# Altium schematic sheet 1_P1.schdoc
size 309 x 223 mm; Symbol: Sheet-Symbol_A4_ByronAP; Device: A4T; @Project Name: Alternator Regulator Field Controller; @Schematic Name: Schematic1; Page Size: A4; @Page Count: 1; @Update Date: 2025-04-14; @Create Date: 2025-04-13; @Page No: 1; @Page Name: P1; Company: ByronAP; Version: 1.0; Drawn: Allen Byron Penner; @Board Name: Board1; @Create Time: 21:01:51; @Update Time: 09:47:18
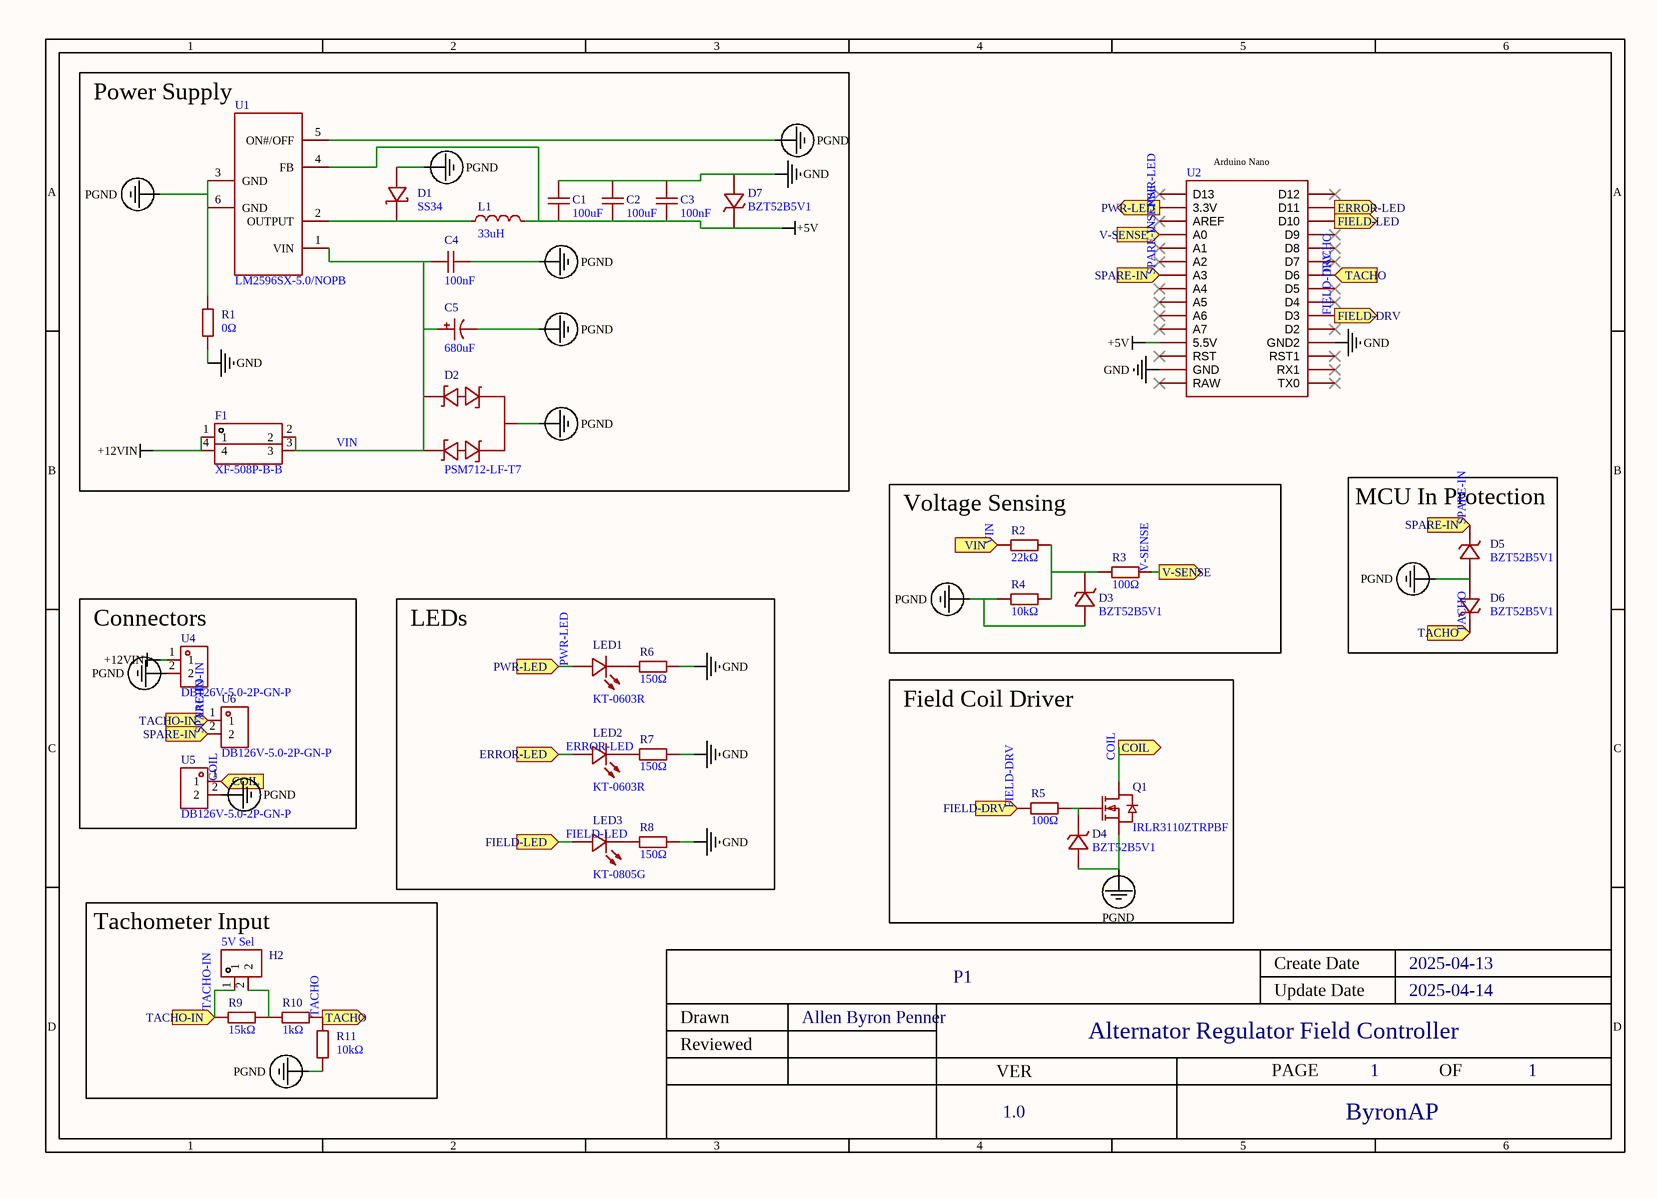
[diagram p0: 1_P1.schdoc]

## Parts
C1  100uF  [C1206]
C2  100uF  [C1206]
C3  100nF  [C1206]
C4  100nF  [C1206]
C5  680uF  [CAP-TH_BD10.0-P5.00-D1.0-FD]
D1  SS34  [SMA_L4.3-W2.6-LS5.2-RD]
D2  PSM712-LF-T7  [SOT-23-3_L3.0-W1.7-P0.95-LS2.9-BR]
D3  BZT52B5V1  [SOD-123_L2.7-W1.6-LS3.7-RD]
D4  BZT52B5V1  [SOD-123_L2.7-W1.6-LS3.7-RD]
D5  BZT52B5V1  [SOD-123_L2.7-W1.6-LS3.7-RD]
D6  BZT52B5V1  [SOD-123_L2.7-W1.6-LS3.7-RD]
D7  BZT52B5V1  [SOD-123_L2.7-W1.6-LS3.7-RD]
F1  XF-508P-B-B  [FUSE-TH_4P-L16.0-W6.7]
H2  PZ254V-11-02P  [HDR-TH_2P-P2.54-V-M]  (value not drawn)
L1  33uH  [IND-SMD_L10.8-W10.0_SLO1040H]
LED1  KT-0603R  [LED0603-RD]
LED2  KT-0603R  [LED0603-RD]
LED3  KT-0805G  [LED0805-R-RD]
Q1  IRLR3110ZTRPBF  [TO-252-3_L6.5-W5.8-P4.58-BL]
R1  0Ω  [R0805]
R2  22kΩ  [R0805]
R3  100Ω  [R0805]
R4  10kΩ  [R0805]
R5  100Ω  [R0805]
R6  150Ω  [R0805]
R7  150Ω  [R0805]
R8  150Ω  [R0805]
R9  15kΩ  [R0805]
R10  1kΩ  [R0805]
R11  10kΩ  [R0805]
U1  LM2596SX-5.0/NOPB  [TO-263-5_L10.2-W8.9-P1.70-TL]
U2  NANO  [NANO]  (value not drawn)
U4  DB126V-5.0-2P-GN-P  [CONN-TH_2P-P5.00_L7.8-W10.0]
U5  DB126V-5.0-2P-GN-P  [CONN-TH_2P-P5.00_L7.8-W10.0]
U6  DB126V-5.0-2P-GN-P  [CONN-TH_2P-P5.00_L7.8-W10.0]

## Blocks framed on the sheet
Power Supply: C1-C5 D1 D2 D7 F1 L1 R1 U1
Voltage Sensing: D3 R2-R4
MCU In Protection: D5 D6
Connectors: U4-U6
LEDs: LED1-LED3 R6-R8
Field Coil Driver: D4 Q1 R5
Tachometer Input: H2 R9-R11

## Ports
COIL (in), COIL (out), ERROR-LED (in), ERROR-LED (out), FIELD-DRV (in), FIELD-DRV (out), FIELD-LED (in), FIELD-LED (out), PWR-LED (in), PWR-LED (out), SPARE-IN (in), TACHO (in), TACHO (out), TACHO-IN (in), V-SENSE (in), V-SENSE (out), VIN (in)

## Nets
+5V: C1.1 C2.1 C3.1 D7.1(K) L1.2 U1.4(FB) U2.5V(5.5V)
+12VIN: F1.1 F1.4 U4.1
GND: C1.2 C2.2 C3.2 D7.2(A) R1.1 R6.2 R7.2 R8.2 U2.GND U2.GND1(GND2)
PGND: C4.2 C5.2 D1.2(A) D2.3(K) D3.2(A) D4.2(A) D5.2(A) D6.2(A) Q1.3(S) R1.2 R4.1 R11.1 U1.3(GND) U1.5(ON#/OFF) U1.6(GND) U4.2 U5.2
COIL: Q1.2(D) U5.1 ; port COIL
ERROR-LED: LED2.2(A) U2.D11 ; port ERROR-LED
FIELD-DRV: R5.1 U2.D3 ; port FIELD-DRV
FIELD-LED: LED3.1(A) U2.D10 ; port FIELD-LED
PWR-LED: LED1.2(A) U2.3.3V ; port PWR-LED
SPARE-IN: D5.1(K) U2.A3 U6.2 ; port SPARE-IN
TACHO: D6.1(K) R10.2 R11.2 U2.D6 ; port TACHO
TACHO-IN: H2.1 R9.1 U6.1 ; port TACHO-IN
V-SENSE: R3.2 U2.A0 ; port V-SENSE
VIN: C4.1 C5.1 D2.1(A1) D2.2(A1) F1.2 F1.3 R2.1 U1.1(VIN) ; port VIN
NetD1_1: D1.1(K) L1.1 U1.2(OUTPUT)
NetD3_1: D3.1(K) R2.2 R3.1 R4.2
NetD4_1: D4.1(K) Q1.1(G) R5.2
NetH2_2: H2.2 R9.2 R10.1
NetLED1_1: LED1.1(K) R6.1
NetLED2_1: LED2.1(K) R7.1
NetLED3_2: LED3.2(K) R8.1

Not connected (* = marked no-connect by the designer): U2 A1* A2* A4* A5* A6* A7* AREF* D2* D4* D5* D7* D8* D9* D12* D13* RAW* RST* RST1* RX1* TX0*

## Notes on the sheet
- (near H2) 5V Sel

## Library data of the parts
C1 C2 = CL31A107MQHNNNE: Manufacturer: SAMSUNG(三星); Add into BOM: yes; Tolerance: ±20%
C3 C4 = CL31B104KBCNNNC: Manufacturer: SAMSUNG(三星); Add into BOM: yes; Tolerance: ±10%
C5 = ERF1EM681G16OT: Manufacturer: AISHI(艾华集团); Add into BOM: yes; Tolerance: ±20%; Voltage Rating: 25V; Pin Spacing: 5mm; Lifetime: 5000hrs@105℃
D1 = SS34_C8678: Manufacturer: MDD(辰达半导体); Add into BOM: yes; Diode Configuration: Independent Type; Forward Voltage (Vf@If): 550mV@3A; Reverse Voltage (Vr): 40V; Rectified Current: 3A; Reverse Leakage Current (Ir): 500uA@40V
D2 = PSM712-LF-T7_C32677: Manufacturer: PROTEK; Add into BOM: yes; Reverse Stand-Off Voltage (Vrwm): 12V; Clamping Voltage: 19V; Voltage - Breakdown: 13.3V; Type: TVS
D3-D7 = BZT52B5V1_C19077393: Manufacturer: 宏嘉诚; Add into BOM: yes; Diode Configuration: Independent Type; Zener Voltage(Nom): 5.1V; Reverse Leakage Current (Ir): 2uA@2V; Zener Voltage(Range): 5V~5.2V; Pd - Power Dissipation(Pd): 500mW; Impedance(Zzt): 60Ω
F1 = XF-508P-B-B: Manufacturer: XFCN(兴飞); Add into BOM: yes
H2 = PZ254V-11-02P: Manufacturer: XFCN(兴飞); Add into BOM: yes; Pin Structure: 1x2P; Pitch: 2.54mm; Circluar Pins/Square Pins: Policy
L1 = SLO1040H330MTT: Manufacturer: Sunltech(韩国顺磁); Add into BOM: yes; Tolerance: ±20%
LED1 LED2 = KT-0603R: Manufacturer: KENTO; Add into BOM: yes; Emitted Color: Red
LED3 = KT-0805G: Manufacturer: KENTO; Symbol: 0805G (Green); Add into BOM: yes; Emitted Color: Emerald
Q1 = IRLR3110ZTRPBF: Manufacturer: Infineon(英飞凌); Add into BOM: yes; Type: 1 N-Channel; Drain Source On Resistance (RDS(on)@Vgs,Id): 14mΩ@10V,38A; Gate Threshold Voltage (Vgs(th)@Id): 2.5V@100uA; Total Gate Charge (Qg@Vgs): 48nC; Input Capacitance (Ciss@Vds): 3980pF; Reverse Transfer Capacitance (Crss@Vds): 130pF
R1 = 0805W8F0000T5E_C17477: Manufacturer: UNI-ROYAL(厚声); Add into BOM: yes; Tolerance: ±1%; Temperature Coefficient: ±800ppm/℃
R2 = 0805W8F2202T5E: Manufacturer: UNI-ROYAL(厚声); Add into BOM: yes; Tolerance: ±1%; Temperature Coefficient: ±100ppm/℃
R3 R5 = 0805W8F1000T5E_C17408: Manufacturer: UNI-ROYAL(厚声); Add into BOM: yes; Tolerance: ±1%; Temperature Coefficient: ±100ppm/℃
R4 R11 = 0805W8F1002T5E: Manufacturer: UNI-ROYAL(厚声); Add into BOM: yes; Tolerance: ±1%; Temperature Coefficient: ±100ppm/℃
R6-R8 = 0805W8F1500T5E: Manufacturer: UNI-ROYAL(厚声); Add into BOM: yes; Tolerance: ±1%; Temperature Coefficient: ±100ppm/℃
R9 = 0805W8F1502T5E: Manufacturer: UNI-ROYAL(厚声); Add into BOM: yes; Tolerance: ±1%; Temperature Coefficient: ±100ppm/℃
R10 = 0805W8F1001T5E: Manufacturer: UNI-ROYAL(厚声); Add into BOM: yes; Tolerance: ±1%; Temperature Coefficient: ±100ppm/℃
U1 = LM2596SX-5.0/NOPB: Manufacturer: TI(德州仪器); Add into BOM: yes; Function: Step-down type; Output Type: Fixed; Input Voltage: 4.5V~40V; Output Voltage: 5V; Output Current: 3A; Switching Frequency: 150kHz; Synchronous Rectification: No; Number of Outputs: 1; Topology: Step-down; Quiescent Current (Iq): 80uA; Switch tube (built-in/external): Built-in
U2 = NANO: Add into BOM: yes; _: 3
U4-U6 = DB126V-5.0-2P-GN-P: Manufacturer: DORABO(地博电气); Add into BOM: yes; Structure: 1x2P; Pitch: 5mm; Current Rating (Max): 15A; Voltage Rating (Max): 250V; Wire Gauge - AWG: 14~26; Wire Gauge - mm2: 1.5; Number of PINs Per Row: 2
